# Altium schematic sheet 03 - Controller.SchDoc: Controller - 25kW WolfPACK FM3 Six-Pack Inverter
size 431 x 279 mm; Date: 09/2024; DocumentNumber: CRD25DA12N-FMC; Revision: 2.0; SheetNumber: 3; SheetTotal: 9; SheetSize: B
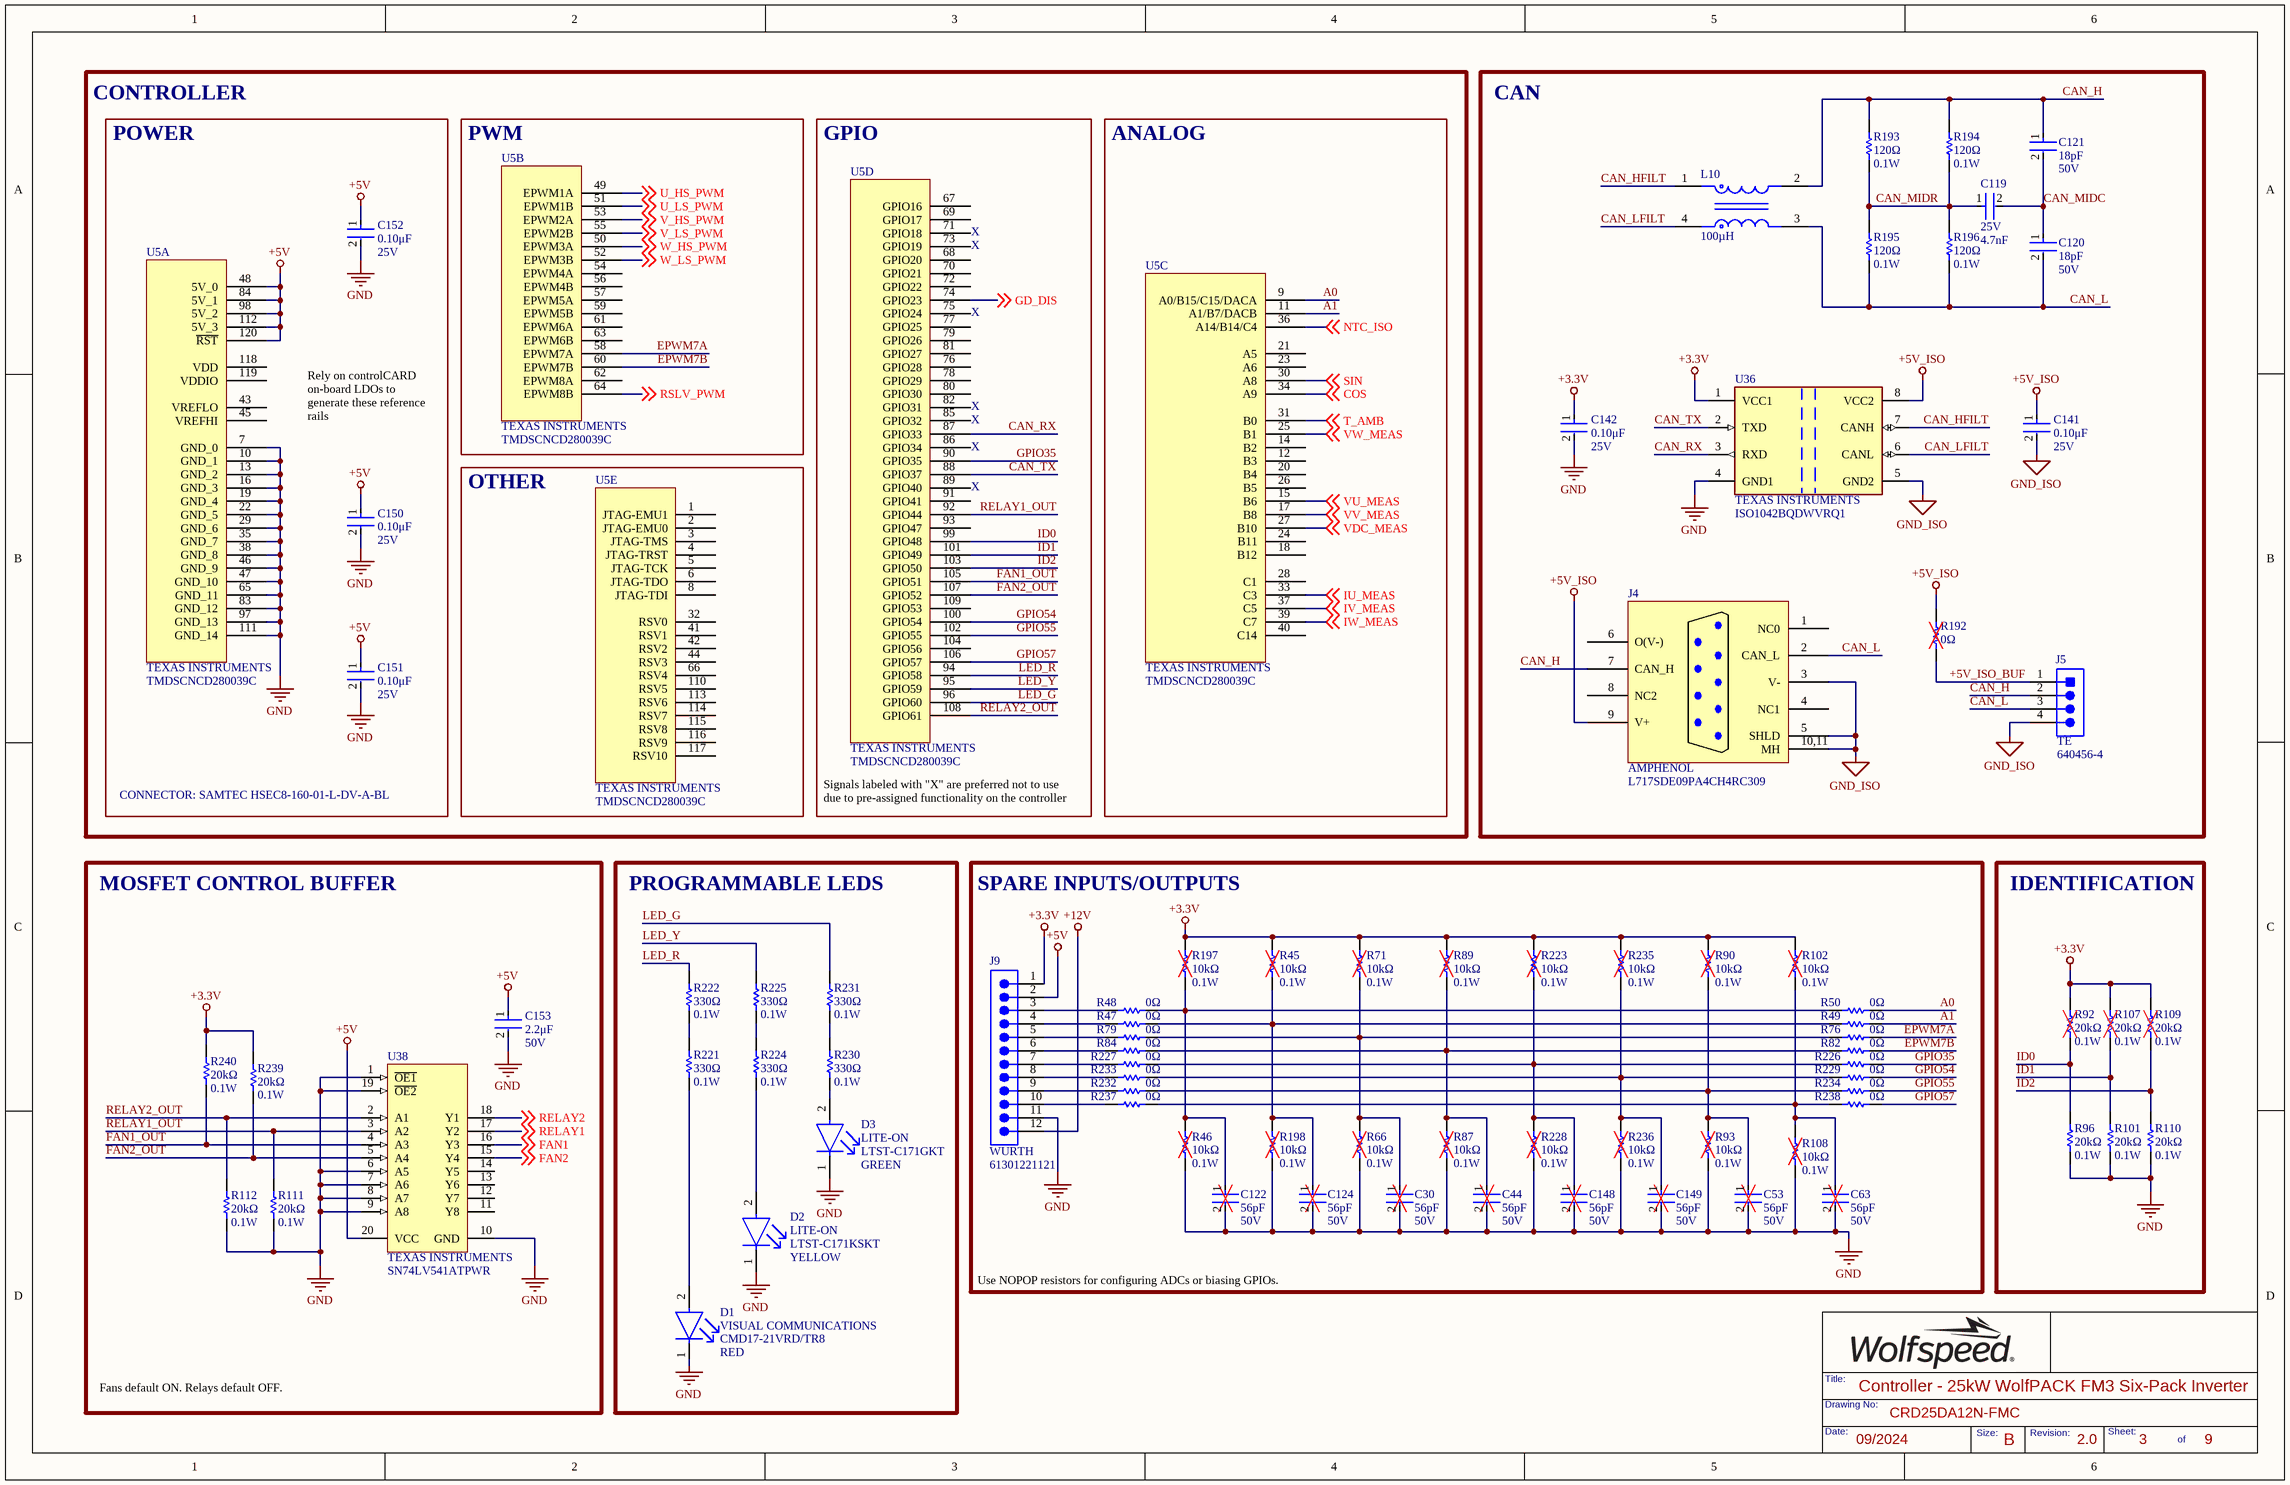
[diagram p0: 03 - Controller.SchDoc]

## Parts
C30  Capacitance: 56pF  Voltage Rating: 50V  [FP-C0603C-CF-IPC_B]  (hidden comment: CL10C560JB8NNNC)
C44  Capacitance: 56pF  Voltage Rating: 50V  [FP-C0603C-CF-IPC_B]  (hidden comment: CL10C560JB8NNNC)
C53  Capacitance: 56pF  Voltage Rating: 50V  [FP-C0603C-CF-IPC_B]  (hidden comment: CL10C560JB8NNNC)
C63  Capacitance: 56pF  Voltage Rating: 50V  [FP-C0603C-CF-IPC_B]  (hidden comment: CL10C560JB8NNNC)
C119  Voltage Rating: 25V  Capacitance: 4.7nF  [FP-C0603C-CF-IPC_B]  (hidden comment: C0603C472K3RAC7867)
C120  Capacitance: 18pF  Voltage Rating: 50V  [FP-C0603C-CF-IPC_B]  (hidden comment: 06035A180JAT2A)
C121  Capacitance: 18pF  Voltage Rating: 50V  [FP-C0603C-CF-IPC_B]  (hidden comment: 06035A180JAT2A)
C122  Capacitance: 56pF  Voltage Rating: 50V  [FP-C0603C-CF-IPC_B]  (hidden comment: CL10C560JB8NNNC)
C124  Capacitance: 56pF  Voltage Rating: 50V  [FP-C0603C-CF-IPC_B]  (hidden comment: CL10C560JB8NNNC)
C141  Voltage Rating: 25V  Capacitance: 0.10μF  [FP-C0603C-CF-IPC_B]  (hidden comment: C0603C104K3RACTU)
C142  Voltage Rating: 25V  Capacitance: 0.10μF  [FP-C0603C-CF-IPC_B]  (hidden comment: C0603C104K3RACTU)
C148  Capacitance: 56pF  Voltage Rating: 50V  [FP-C0603C-CF-IPC_B]  (hidden comment: CL10C560JB8NNNC)
C149  Capacitance: 56pF  Voltage Rating: 50V  [FP-C0603C-CF-IPC_B]  (hidden comment: CL10C560JB8NNNC)
C150  Voltage Rating: 25V  Capacitance: 0.10μF  [FP-C0603C-CF-IPC_B]  (hidden comment: C0603C104K3RACTU)
C151  Voltage Rating: 25V  Capacitance: 0.10μF  [FP-C0603C-CF-IPC_B]  (hidden comment: C0603C104K3RACTU)
C152  Voltage Rating: 25V  Capacitance: 0.10μF  [FP-C0603C-CF-IPC_B]  (hidden comment: C0603C104K3RACTU)
C153  Voltage Rating: 50V  Capacitance: 2.2μF  [FP-C0603C-CF-IPC_B]  (hidden comment: GRT188R61H225ME13D)
D1  value RED  Manufacturer: VISUAL COMMUNICATIONS  [FP-LTST-C171GKT-MFG-RED]  (hidden comment: CMD17-21VRD/TR8)
D2  LTST-C171KSKT  value YELLOW  Manufacturer: LITE-ON  [FP-LTST-C171GKT-MFG-YELLOW]
D3  value GREEN  Manufacturer: LITE-ON  [FP-LTST-C171GKT-MFG]  (hidden comment: LTST-C171GKT)
J4  Manufacturer: AMPHENOL  [L717SDE09PA4CH4RC309]  (hidden comment: L717SDE09PA4CH4RC309)
J5  Manufacturer: TE  [TECO-640456-4]  (hidden comment: 640456-4)
J9  Manufacturer Print: WURTH  [FP-61301221121-MFG]  (hidden comment: 61301221121)
L10  value 100µH  [FP-DLW43-0_2-t2_6-e0_6-MFG]  (hidden comment: DLW43SH101XK2L)
R45  Resistance: 10kΩ  Max Power Dissipation: 0.1W  [FP-MCR03-IPC_B]  (hidden comment: ERJ3EKF1002V)
R46  Resistance: 10kΩ  Max Power Dissipation: 0.1W  [FP-MCR03-IPC_B]  (hidden comment: ERJ3EKF1002V)
R47  Resistance: 0Ω  [FP-MCR03-IPC_B]  (hidden comment: CRCW06030000Z0EB)
R48  Resistance: 0Ω  [FP-MCR03-IPC_B]  (hidden comment: CRCW06030000Z0EB)
R49  Resistance: 0Ω  [FP-MCR03-IPC_B]  (hidden comment: CRCW06030000Z0EB)
R50  Resistance: 0Ω  [FP-MCR03-IPC_B]  (hidden comment: CRCW06030000Z0EB)
R66  Resistance: 10kΩ  Max Power Dissipation: 0.1W  [FP-MCR03-IPC_B]  (hidden comment: ERJ3EKF1002V)
R71  Resistance: 10kΩ  Max Power Dissipation: 0.1W  [FP-MCR03-IPC_B]  (hidden comment: ERJ3EKF1002V)
R76  Resistance: 0Ω  [FP-MCR03-IPC_B]  (hidden comment: CRCW06030000Z0EB)
R79  Resistance: 0Ω  [FP-MCR03-IPC_B]  (hidden comment: CRCW06030000Z0EB)
R82  Resistance: 0Ω  [FP-MCR03-IPC_B]  (hidden comment: CRCW06030000Z0EB)
R84  Resistance: 0Ω  [FP-MCR03-IPC_B]  (hidden comment: CRCW06030000Z0EB)
R87  Resistance: 10kΩ  Max Power Dissipation: 0.1W  [FP-MCR03-IPC_B]  (hidden comment: ERJ3EKF1002V)
R89  Resistance: 10kΩ  Max Power Dissipation: 0.1W  [FP-MCR03-IPC_B]  (hidden comment: ERJ3EKF1002V)
R90  Resistance: 10kΩ  Max Power Dissipation: 0.1W  [FP-MCR03-IPC_B]  (hidden comment: ERJ3EKF1002V)
R92  Resistance: 20kΩ  Power Rating: 0.1W  [FP-MCR03-IPC_B]  (hidden comment: CRCW060320K0FKTA)
R93  Resistance: 10kΩ  Max Power Dissipation: 0.1W  [FP-MCR03-IPC_B]  (hidden comment: ERJ3EKF1002V)
R96  Resistance: 20kΩ  Power Rating: 0.1W  [FP-MCR03-IPC_B]  (hidden comment: CRCW060320K0FKTA)
R101  Resistance: 20kΩ  Power Rating: 0.1W  [FP-MCR03-IPC_B]  (hidden comment: CRCW060320K0FKTA)
R102  Resistance: 10kΩ  Max Power Dissipation: 0.1W  [FP-MCR03-IPC_B]  (hidden comment: ERJ3EKF1002V)
R107  Resistance: 20kΩ  Power Rating: 0.1W  [FP-MCR03-IPC_B]  (hidden comment: CRCW060320K0FKTA)
R108  Resistance: 10kΩ  Max Power Dissipation: 0.1W  [FP-MCR03-IPC_B]  (hidden comment: ERJ3EKF1002V)
R109  Resistance: 20kΩ  Power Rating: 0.1W  [FP-MCR03-IPC_B]  (hidden comment: CRCW060320K0FKTA)
R110  Resistance: 20kΩ  Power Rating: 0.1W  [FP-MCR03-IPC_B]  (hidden comment: CRCW060320K0FKTA)
R111  Resistance: 20kΩ  Power Rating: 0.1W  [FP-MCR03-IPC_B]  (hidden comment: CRCW060320K0FKTA)
R112  Resistance: 20kΩ  Power Rating: 0.1W  [FP-MCR03-IPC_B]  (hidden comment: CRCW060320K0FKTA)
R192  Resistance: 0Ω  [FP-MCR03-IPC_B]  (hidden comment: CRCW06030000Z0EB)
R193  value 120Ω  Max Power Dissipation: 0.1W  [FP-MCR03-IPC_B]  (hidden comment: RC0603JR-07120RL)
R194  value 120Ω  Max Power Dissipation: 0.1W  [FP-MCR03-IPC_B]  (hidden comment: RC0603JR-07120RL)
R195  value 120Ω  Max Power Dissipation: 0.1W  [FP-MCR03-IPC_B]  (hidden comment: RC0603JR-07120RL)
R196  value 120Ω  Max Power Dissipation: 0.1W  [FP-MCR03-IPC_B]  (hidden comment: RC0603JR-07120RL)
R197  Resistance: 10kΩ  Max Power Dissipation: 0.1W  [FP-MCR03-IPC_B]  (hidden comment: ERJ3EKF1002V)
R198  Resistance: 10kΩ  Max Power Dissipation: 0.1W  [FP-MCR03-IPC_B]  (hidden comment: ERJ3EKF1002V)
R221  Resistance: 330Ω  Power Rating: 0.1W  [FP-MCR03-IPC_B]  (hidden comment: RC0603FR-13330RL)
R222  Resistance: 330Ω  Power Rating: 0.1W  [FP-MCR03-IPC_B]  (hidden comment: RC0603FR-13330RL)
R223  Resistance: 10kΩ  Max Power Dissipation: 0.1W  [FP-MCR03-IPC_B]  (hidden comment: ERJ3EKF1002V)
R224  Resistance: 330Ω  Power Rating: 0.1W  [FP-MCR03-IPC_B]  (hidden comment: RC0603FR-13330RL)
R225  Resistance: 330Ω  Power Rating: 0.1W  [FP-MCR03-IPC_B]  (hidden comment: RC0603FR-13330RL)
R226  Resistance: 0Ω  [FP-MCR03-IPC_B]  (hidden comment: CRCW06030000Z0EB)
R227  Resistance: 0Ω  [FP-MCR03-IPC_B]  (hidden comment: CRCW06030000Z0EB)
R228  Resistance: 10kΩ  Max Power Dissipation: 0.1W  [FP-MCR03-IPC_B]  (hidden comment: ERJ3EKF1002V)
R229  Resistance: 0Ω  [FP-MCR03-IPC_B]  (hidden comment: CRCW06030000Z0EB)
R230  Resistance: 330Ω  Power Rating: 0.1W  [FP-MCR03-IPC_B]  (hidden comment: RC0603FR-13330RL)
R231  Resistance: 330Ω  Power Rating: 0.1W  [FP-MCR03-IPC_B]  (hidden comment: RC0603FR-13330RL)
R232  Resistance: 0Ω  [FP-MCR03-IPC_B]  (hidden comment: CRCW06030000Z0EB)
R233  Resistance: 0Ω  [FP-MCR03-IPC_B]  (hidden comment: CRCW06030000Z0EB)
R234  Resistance: 0Ω  [FP-MCR03-IPC_B]  (hidden comment: CRCW06030000Z0EB)
R235  Resistance: 10kΩ  Max Power Dissipation: 0.1W  [FP-MCR03-IPC_B]  (hidden comment: ERJ3EKF1002V)
R236  Resistance: 10kΩ  Max Power Dissipation: 0.1W  [FP-MCR03-IPC_B]  (hidden comment: ERJ3EKF1002V)
R237  Resistance: 0Ω  [FP-MCR03-IPC_B]  (hidden comment: CRCW06030000Z0EB)
R238  Resistance: 0Ω  [FP-MCR03-IPC_B]  (hidden comment: CRCW06030000Z0EB)
R239  Resistance: 20kΩ  Power Rating: 0.1W  [FP-MCR03-IPC_B]  (hidden comment: CRCW060320K0FKTA)
R240  Resistance: 20kΩ  Power Rating: 0.1W  [FP-MCR03-IPC_B]  (hidden comment: CRCW060320K0FKTA)
U5  TMDSCNCD280039C  Manufacturer: TEXAS INSTRUMENTS  [TMDSCNCD280039C]  (parts A,B,C,D,E of 5)
U36  Manufacturer: TEXAS INSTRUMENTS  [FP-DWV0008A-IPC_B]  (hidden comment: ISO1042BQDWVRQ1)
U38  Manufacturer: TEXAS INSTRUMENTS  [PW0020A_L]  (hidden comment: SN74LV541ATPWR)

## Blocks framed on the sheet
CAN: C119-C121 C141 C142 J4 J5 L10 R192-R196 U36
POWER: C150-C152 U5
PWM: U5
GPIO: U5
ANALOG: U5
OTHER: U5
MOSFET CONTROL BUFFER: C153 R111 R112 R239 R240 U38
PROGRAMMABLE LEDS: D1-D3 R221 R222 R224 R225 R230 R231
SPARE INPUTS/OUTPUTS: C30 C44 C53 C63 C122 C124 C148 C149 J9 R45-R50 R66 R71 R76 R79 R82 R84 R87 R89 R90 R93 R102 R108 R197 R198 R223 R226-R229 R232-R238
IDENTIFICATION: R92 R96 R101 R107 R109 R110

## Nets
+3.3V: C142.1 J9.1 R45.2 R71.2 R89.2 R90.2 R92.2 R102.2 R107.2 R109.2 R197.2 R223.2 R235.2 R239.2 R240.2 U36.1(VCC1)
+5V: C150.1 C151.1 C152.1 C153.1 J9.2 U5.48(5V_0) U5.84(5V_1) U5.98(5V_2) U5.112(5V_3) U5.120(~{RST}) U38.20(VCC)
+5V_ISO: C141.1 J4.9(V+) R192.2 U36.8(VCC2)
+12V: J9.12
GND: C30.2 C44.2 C53.2 C63.2 C122.2 C124.2 C142.2 C148.2 C149.2 C150.2 C151.2 C152.2 C153.2 D1.1(C) D2.1(C) D3.1(C) J9.11 R46.1 R66.1 R87.1 R93.1 R96.1 R101.1 R108.1 R110.1 R111.1 R112.1 R198.1 R228.1 R236.1 U5.7(GND_0) U5.10(GND_1) U5.13(GND_2) U5.16(GND_3) U5.19(GND_4) U5.22(GND_5) U5.29(GND_6) U5.35(GND_7) U5.38(GND_8) U5.46(GND_9) U5.47(GND_10) U5.65(GND_11) U5.83(GND_12) U5.97(GND_13) U5.111(GND_14) U36.4(GND1) U38.1(~{OE1}) U38.6(A5) U38.7(A6) U38.8(A7) U38.9(A8) U38.10(GND) U38.19(~{OE2})
GND_ISO: C141.2 J4.3(V-) J4.5(SHLD) J4.10,11(MH) J5.4 U36.5(GND2)
+5V_ISO_BUF: J5.1 R192.1
A0: R50.2 U5.9(A0/B15/C15/DACA)
A1: R49.2 U5.11(A1/B7/DACB)
CAN_H: C121.1 J4.7(CAN_H) J5.2 L10.2 R193.2 R194.2
CAN_HFILT: L10.1 U36.7(CANH)
CAN_L: C120.2 J4.2(CAN_L) J5.3 L10.3 R195.1 R196.1
CAN_LFILT: L10.4 U36.6(CANL)
CAN_MIDC: C119.2 C120.1 C121.2
CAN_MIDR: C119.1 R193.1 R194.1 R195.2 R196.2
CAN_RX: U5.87(GPIO33) U36.3(RXD)
CAN_TX: U5.88(GPIO37) U36.2(TXD)
COS: U5.34(A9) ; off-sheet COS
EPWM7A: R76.2 U5.58(EPWM7A)
EPWM7B: R82.2 U5.60(EPWM7B)
FAN1: U38.16(Y3) ; off-sheet FAN1
FAN1_OUT: R240.1 U5.105(GPIO51) U38.4(A3)
FAN2: U38.15(Y4) ; off-sheet FAN2
FAN2_OUT: R239.1 U5.107(GPIO52) U38.5(A4)
GD_DIS: U5.74(GPIO23) ; off-sheet GD_DIS
GPIO35: R226.2 U5.90(GPIO35)
GPIO54: R229.2 U5.100(GPIO54)
GPIO55: R234.2 U5.102(GPIO55)
GPIO57: R238.2 U5.106(GPIO57)
ID0: R92.1 R96.2 U5.99(GPIO48)
ID1: R101.2 R107.1 U5.101(GPIO49)
ID2: R109.1 R110.2 U5.103(GPIO50)
IU_MEAS: U5.33(C3) ; off-sheet IU_MEAS
IV_MEAS: U5.37(C5) ; off-sheet IV_MEAS
IW_MEAS: U5.39(C7) ; off-sheet IW_MEAS
LED_G: R231.2 U5.96(GPIO60)
LED_R: R222.2 U5.94(GPIO58)
LED_Y: R225.2 U5.95(GPIO59)
NTC_ISO: U5.36(A14/B14/C4) ; off-sheet NTC_ISO
RELAY1: U38.17(Y2) ; off-sheet RELAY1
RELAY1_OUT: R111.2 U5.92(GPIO44) U38.3(A2)
RELAY2: U38.18(Y1) ; off-sheet RELAY2
RELAY2_OUT: R112.2 U5.108(GPIO61) U38.2(A1)
RSLV_PWM: U5.64(EPWM8B) ; off-sheet RSLV_PWM
SIN: U5.30(A8) ; off-sheet SIN
T_AMB: U5.31(B0) ; off-sheet T_AMB
U_HS_PWM: U5.49(EPWM1A) ; off-sheet U_HS_PWM
U_LS_PWM: U5.51(EPWM1B) ; off-sheet U_LS_PWM
V_HS_PWM: U5.53(EPWM2A) ; off-sheet V_HS_PWM
V_LS_PWM: U5.55(EPWM2B) ; off-sheet V_LS_PWM
VDC_MEAS: U5.27(B10) ; off-sheet VDC_MEAS
VU_MEAS: U5.15(B6) ; off-sheet VU_MEAS
VV_MEAS: U5.17(B8) ; off-sheet VV_MEAS
VW_MEAS: U5.25(B1) ; off-sheet VW_MEAS
W_HS_PWM: U5.50(EPWM3A) ; off-sheet W_HS_PWM
W_LS_PWM: U5.52(EPWM3B) ; off-sheet W_LS_PWM
NetC30_1: C30.1 R66.2 R71.1 R76.1 R79.2
NetC44_1: C44.1 R82.1 R84.2 R87.2 R89.1
NetC53_1: C53.1 R90.1 R93.2 R232.2 R234.1
NetC63_1: C63.1 R102.1 R108.2 R237.2 R238.1
NetC122_1: C122.1 R46.2 R48.2 R50.1 R197.1
NetC124_1: C124.1 R45.1 R47.2 R49.1 R198.2
NetC148_1: C148.1 R223.1 R226.1 R227.2 R228.2
NetC149_1: C149.1 R229.1 R233.2 R235.1 R236.2
NetD1_2: D1.2(A) R221.1
NetD2_2: D2.2(A) R224.1
NetD3_2: D3.2(A) R230.1
NetJ9_3: J9.3 R48.1
NetJ9_4: J9.4 R47.1
NetJ9_5: J9.5 R79.1
NetJ9_6: J9.6 R84.1
NetJ9_7: J9.7 R227.1
NetJ9_8: J9.8 R233.1
NetJ9_9: J9.9 R232.1
NetJ9_10: J9.10 R237.1
NetR221_2: R221.2 R222.1
NetR224_2: R224.2 R225.1
NetR230_2: R230.2 R231.1

Not connected (* = marked no-connect by the designer): J4 1(NC0) 4(NC1) 6(O(V-)) 8(NC2); U5 1(JTAG-EMU1) 2(JTAG-EMU0) 3(JTAG-TMS) 4(JTAG-TRST) 5(JTAG-TCK) 6(JTAG-TDO) 8(JTAG-TDI) 12(B3) 14(B2) 18(B12) 20(B4) 21(A5) 23(A6) 24(B11) 26(B5) 28(C1) 32(RSV0) 40(C14) 41(RSV1) 42(RSV2) 43(VREFLO) 44(RSV3) 45(VREFHI) 54(EPWM4A) 56(EPWM4B) 57(EPWM5A) 59(EPWM5B) 61(EPWM6A) 62(EPWM8A) 63(EPWM6B) 66(RSV4) 67(GPIO16) 68(GPIO20) 69(GPIO17) 70(GPIO21) 71(GPIO18) 72(GPIO22) 73(GPIO19) 75(GPIO24) 76(GPIO28) 77(GPIO25) 78(GPIO29) 79(GPIO26) 80(GPIO30) 81(GPIO27) 82(GPIO31) 85(GPIO32) 86(GPIO34) 89(GPIO40) 91(GPIO41) 93(GPIO47) 104(GPIO56) 109(GPIO53) 110(RSV5) 113(RSV6) 114(RSV7) 115(RSV8) 116(RSV9) 117(RSV10) 118(VDD) 119(VDDIO); U38 11(Y8) 12(Y7) 13(Y6) 14(Y5)

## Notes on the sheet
- CONTROLLER
- (near U5) X
- Rely on controlCARD on-board LDOs to generate these reference rails
- CONNECTOR: SAMTEC HSEC8-160-01-L-DV-A-BL
- Signals labeled with "X" are preferred not to use due to pre-assigned functionality on the controller
- Use NOPOP resistors for configuring ADCs or biasing GPIOs.
- Fans default ON. Relays default OFF.

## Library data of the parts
C30 C44 C53 C63 C122 C124 C148 C149 = CL10C560JB8NNNC: CAP CER 56PF 50V C0G/NP0 0603; Manufacturer: SAMSUNG; Material: Ceramic; Tolerance: 5%; Dielectric: C0G; Temperature Coefficient: 30ppm/°C
C119 = C0603C472K3RAC7867: CAP CER 4700PF 25V 10% X7R 0603; Manufacturer: KEMET; Manufacturer Part Number: C0603C472K3RACTU; Dielectric Material: Ceramic; Value: 4.7nF
C120 C121 = 06035A180JAT2A: CAP CER 18PF 50V C0G/NP0 0603; Manufacturer: KYOCERA AVX; Dielectric Material: Ceramic; Tolerance: 5%; Dielectric: C0G; Insulation Resistance: 100GR; Temperature Coefficient: 30ppm/°C
C141 C142 C150-C152 = CMP-2006-03057-2: CAP CER 0.1UF 25V X7R 0603; Manufacturer: KEMET; Value: 0.10μF; Material: Ceramic; Tolerance: 0.1; Temperature Coefficient: 30ppm/°C; Automotive Grade: Grade 1
C153 = GRT188R61H225ME13D: CAP CER 2.2UF 50V X5R 0603; Manufacturer: MURATA; Tolerance: 20%; Value: 2.2μF
D1 = CMD17-21VRD/TR8: LED RED DIFFUSED 0805 SMD; Power Rating: 100mW; Luminous Intensity: 6mcd; Viewing Angle: 140°; Lens Style: Diffused,Tinted,Rectangular,Colored; Forward Current: 20mA; Forward Voltage: 2V; Wavelength: 640nm; Reverse Voltage (DC): 5V; Number of LEDs: 1
D2 = LTST-C171KSKT: LED YELLOW CLEAR 0805 SMD; Lens Color: Colorless; Number of LEDs: 1; Reverse Voltage: 5V; Viewing Angle: 130°; Lens Style: Diffused,Colorless,Rectangular,Clear; Luminous Intensity: 50mcd; Forward Voltage: 2V; Dominant Wavelength: 587nm; Test Current: 20mA; Wavelength: 588nm; Forward Current: 30mA; Max Power Dissipation: 75mW
D3 = CMP-22017-000007-1: LED GREEN CLEAR CHIP SMD; Luminous Intensity: 12mcd; Lens Color: Colorless; Dominant Wavelength: 569nm; Number of LEDs: 1; Power Dissipation: 100mW; Viewing Angle: 130°; Reverse Voltage: 5V; Test Current: 10mA; Forward Voltage: 2.1V; Wavelength: 585nm; Lens Style: Diffused; Forward Current: 30mA
J4 = L717SDE09PA4CH4RC309: CONN D-SUB PLUG 9POS R/A SLDR; Number of Terminals/Pins: 9; Connector Type: D-Sub,Plug; Voltage Rating: 250V; Current Rating: 5A; Number of Ports: 1; Pitch: 2.74mm
J5 = CMP-2000-05419-1: CONN HEADER VERT 4POS 2.54MM; Material, Housing: Polyester; Primary Type: InterconnectSystem; Mount Angle: Vertical; Color, Housing: White; Current, Rating: 5 / A; Agency Approvals: CSA,UL; Contact Termination Area Plating: Tin; Temperature, Operating: -55to+105 / degC; Standards: RoHSCompliant,ELVCompliant,UL94V-0; Number of Positions: 4; Brand/Series: MTA-100Series; Angle: Straight; Pin Spacing: 0.1 / "; Material, Contact: CopperAlloy; Connector Type: MTA-100; Special Features: Pinstrip; Mounting Hole Size: 0.04 / "; Contact Centerline Spacing: 0.100 / in.; Voltage, Rating: 250 / V
J9 = 61301221121: CONN HEADER VERT 12POS 2.54MM; Manufacturer: WURTH ELEKTRONIK; Number of Positions: 12; Gender: Male; Voltage Rating: 250V; Pitch: 0.1inch
L10 = CMP-006-00021-3: CMC 100UH 200MA 2LN SMD AEC-Q200; Manufacturer: MURATA
R45 R46 R66 R71 R87 R89 R90 R93 R102 R108 R197 R198 R223 R228 R235 R236 = ERJ3EKF1002V: RES SMD 10K OHM 1% 1/10W 0603; Manufacturer: PANASONIC; Manufacturer Part Number: ERJ-3EKF1002V; Temperature Coefficient: 100ppm/°C; Power Rating: 100mW; Voltage Rating: 75V; Value: 10kΩ
R47-R50 R76 R79 R82 R84 R192 R226 R227 R229 R232-R234 R237 R238 = CRCW06030000Z0EB: RES SMD 0 OHM JUMPER 1/10W 0603; Manufacturer: VISHAY DALE; Manufacturer Part Number: CRCW06030000Z0EBC; Max Power Dissipation: 100mW; Voltage Rating: 75V; Tolerance: 1%; Temperature Coefficient: 100ppm/°C; Value: 0Ω
R92 R96 R101 R107 R109-R112 R239 R240 = CRCW060320K0FKTA: RES SMD 20K OHM 1% 1/10W 0603; Manufacturer: VISHAY DALE; Temperature Coefficient: 100ppm/°C; Voltage Rating: 75V; Max Power Dissipation: 100mW; Value: 20kΩ
R193-R196 = RC0603JR-07120RL: RES 120 OHM 5% 1/10W 0603; Manufacturer: YAGEO; Voltage Rating (DC): 50V; Temperature Coefficient: 100ppm/°C; Power Rating: 100mW
R221 R222 R224 R225 R230 R231 = RC0603FR-13330RL: RES 330 OHM 1% 1/10W 0603; Manufacturer: YAGEO; Voltage Rating: 50V; Temperature Coefficient: 100ppm/°C; Value: 330Ω
U5 = TMDSCNCD280039C: EVAL BOARD FOR TMS320F280039C
U36 = CMP-04872-000086-1: IC TXRX/ISO FULL 1/1 8SOIC
U38 = CMP-0440-01163-3: IC BUF NON-INVERT 5.5V 20TSSOP; Bits(#): 8; Voltage(Nom)(V): 5; ICC @ Nom Voltage(Max)(mA): 0.02; VCC(Max)(V): 5.5; Output Type: CMOS; Rating: Catalog; Input Type: TTL; VCC(Min)(V): 4.5; F @ Nom Voltage(Max)(Mhz): 110; tpd @ Nom Voltage(Max)(ns): 7.9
